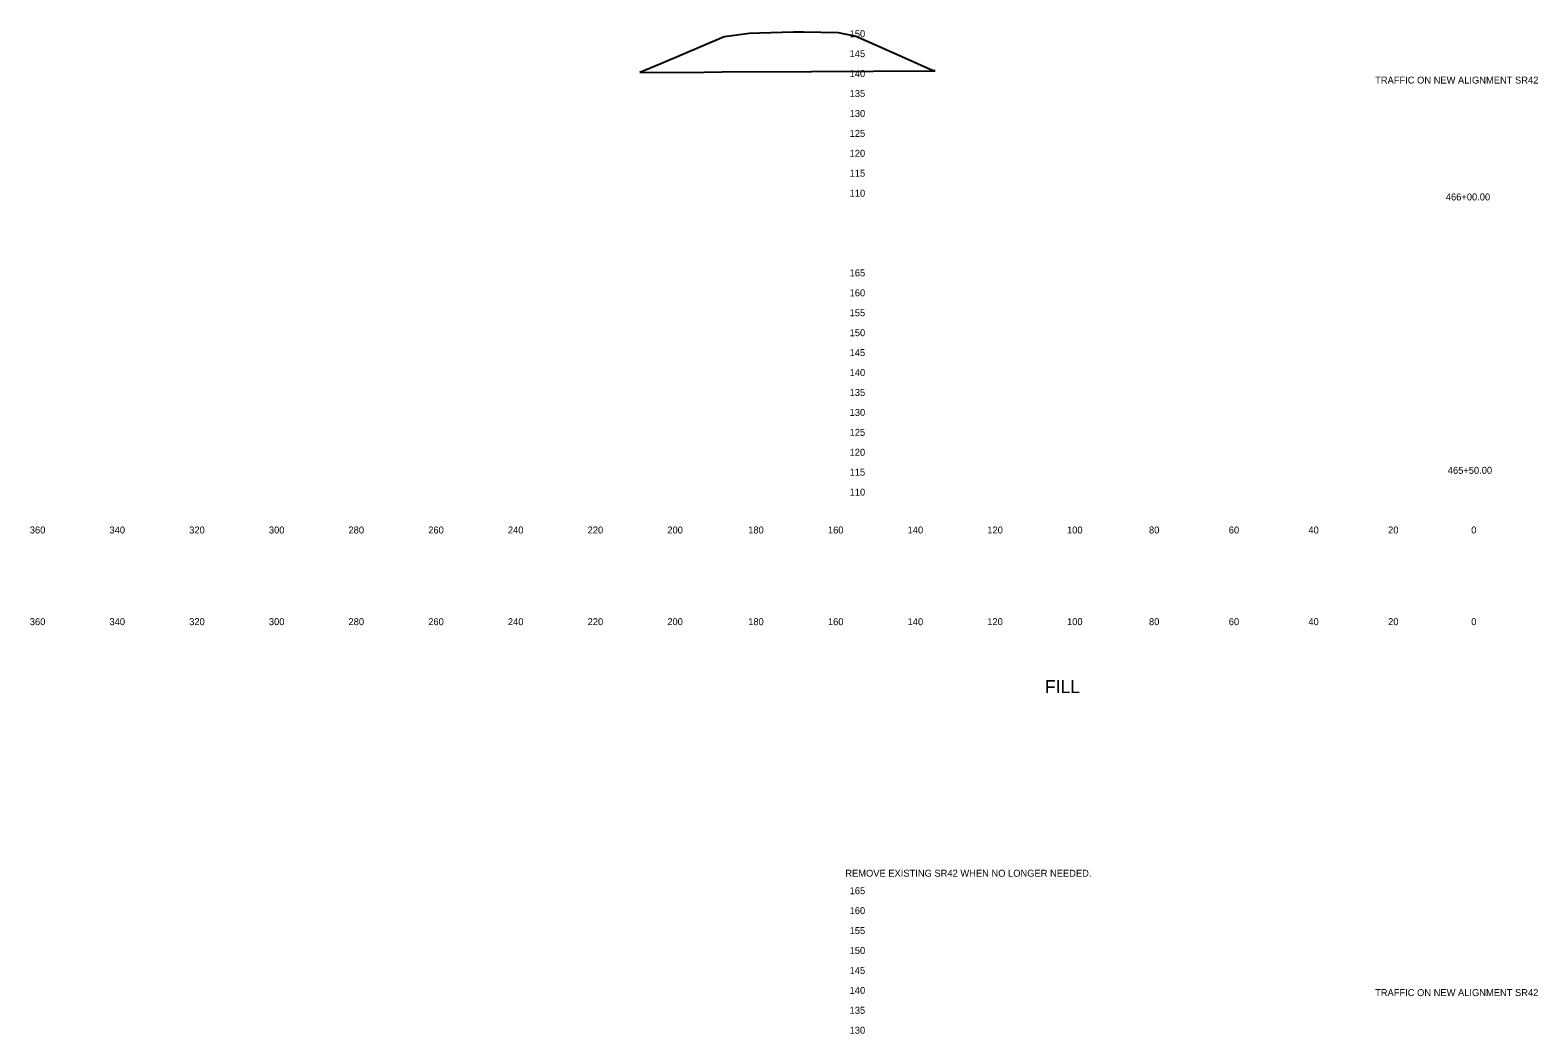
# Model space of a CAD drawing. Extents: x 21281 to 22024, y 6472 to 15208.
# Drawn here: x 21280.5 to 21658.8, y 8649.8 to 8901.6 of the extents above; entities that cross this region are included whole.
import ezdxf

# ---------------------------------------------------------------- set-up
doc = ezdxf.new("R2010")
doc.units = 0
for name, color, linetype in [('XS_SHEET_LABELS_ELEVATION', 7, 'Continuous'), ('XS_SHEET_LABELS_OFFSET', 7, 'Continuous'), ('XS_SHEET_LABELS_STATION', 7, 'Continuous'), ('XS_X_EXCESS', 7, 'Continuous')]:
    doc.layers.add(name, color=color, linetype=linetype)

msp = doc.modelspace()

# ---------------------------------------------------------------- linework, layer by layer
at = {"layer": 'XS_X_EXCESS'}
msp.add_line((21507.64, 8891.41), (21507.07, 8891.44), dxfattribs=at)
for points in [[(21507.07, 8891.44), (21495.34, 8896.65), (21487.51, 8900.14), (21484.92, 8900.63), (21483.38, 8900.95), (21474.61, 8901.09), (21472.04, 8901.15), (21463.53, 8900.89), (21460.9, 8900.81), (21455.98, 8900.1), (21454.68, 8899.97), (21438.79, 8893.18), (21433.47, 8891.02)], [(21433.47, 8891.02), (21449.64, 8891.11), (21454.14, 8891.14), (21476.57, 8891.26), (21507.64, 8891.41)]]:
    msp.add_lwpolyline(points, dxfattribs=at)

# ---------------------------------------------------------------- texts
at = {"layer": 'XS_SHEET_LABELS_ELEVATION'}
for s, p in [('  150  ', (21484.84, 8899.84)), ('  145  ', (21484.84, 8894.84)), ('  140  ', (21484.84, 8889.84)), ('  135  ', (21484.84, 8884.84)), ('  130  ', (21484.84, 8879.84)), ('  125  ', (21484.84, 8874.84)), ('  120  ', (21484.84, 8869.84)), ('  115  ', (21484.84, 8864.84)), ('  110  ', (21484.84, 8859.84)), ('  165  ', (21484.84, 8839.84)), ('  160  ', (21484.84, 8834.84)), ('  155  ', (21484.84, 8829.84)), ('  150  ', (21484.84, 8824.84)), ('  145  ', (21484.84, 8819.84)), ('  140  ', (21484.84, 8814.84)), ('  135  ', (21484.84, 8809.84)), ('  130  ', (21484.84, 8804.84)), ('  125  ', (21484.84, 8799.84)), ('  120  ', (21484.84, 8794.84)), ('  115  ', (21484.84, 8789.84)), ('  110  ', (21484.84, 8784.84)), ('  165  ', (21484.84, 8684.84)), ('  160  ', (21484.84, 8679.84)), ('  155  ', (21484.84, 8674.84)), ('  150  ', (21484.84, 8669.84)), ('  145  ', (21484.84, 8664.84)), ('  140  ', (21484.84, 8659.84)), ('  135  ', (21484.84, 8654.84)), ('  130  ', (21484.84, 8649.84))]:
    msp.add_text(s, height=1.75, dxfattribs=at).set_placement(p)
at = {"layer": 'XS_SHEET_LABELS_OFFSET'}
for s, height, p in [('  360  ', 1.75, (21279.14, 8775.34)), ('  340  ', 1.75, (21299.13, 8775.34)), ('  320  ', 1.75, (21319.13, 8775.34)), ('  300  ', 1.75, (21339.13, 8775.34)), ('  280  ', 1.75, (21359.1, 8775.34)), ('  260  ', 1.75, (21379.11, 8775.34)), ('  240  ', 1.75, (21399.1, 8775.34)), ('  220  ', 1.75, (21419.1, 8775.34)), ('  200  ', 1.75, (21439.1, 8775.34)), ('  180  ', 1.75, (21459.39, 8775.34)), ('  160  ', 1.75, (21479.4, 8775.34)), ('  140  ', 1.75, (21499.39, 8775.34)), ('  120  ', 1.75, (21519.39, 8775.34)), ('  100  ', 1.75, (21539.39, 8775.34)), ('  80  ', 1.75, (21559.95, 8775.34)), ('  60  ', 1.75, (21579.97, 8775.34)), ('  40  ', 1.75, (21599.95, 8775.34)), ('  20  ', 1.75, (21619.95, 8775.34)), ('  0  ', 1.75, (21640.81, 8775.34)), ('  0  ', 1.75, (21640.81, 8775.34)), ('  360  ', 1.75, (21279.14, 8752.34)), ('  340  ', 1.75, (21299.13, 8752.34)), ('  320  ', 1.75, (21319.13, 8752.34)), ('  300  ', 1.75, (21339.13, 8752.34)), ('  280  ', 1.75, (21359.1, 8752.34)), ('  260  ', 1.75, (21379.11, 8752.34)), ('  240  ', 1.75, (21399.1, 8752.34)), ('  220  ', 1.75, (21419.1, 8752.34)), ('  200  ', 1.75, (21439.1, 8752.34)), ('  180  ', 1.75, (21459.39, 8752.34)), ('  160  ', 1.75, (21479.4, 8752.34)), ('  140  ', 1.75, (21499.39, 8752.34)), ('  120  ', 1.75, (21519.39, 8752.34)), ('  100  ', 1.75, (21539.39, 8752.34)), ('  80  ', 1.75, (21559.95, 8752.34)), ('  60  ', 1.75, (21579.97, 8752.34)), ('  40  ', 1.75, (21599.95, 8752.34)), ('  20  ', 1.75, (21619.95, 8752.34)), ('  0  ', 1.75, (21640.81, 8752.34)), ('  0  ', 1.75, (21640.81, 8752.34)), ('FILL', 3.273, (21535.18, 8735.29))]:
    msp.add_text(s, height=height, dxfattribs=at).set_placement(p)
at = {"layer": 'XS_SHEET_LABELS_STATION'}
for s, p in [('TRAFFIC ON NEW ALIGNMENT SR42', (21617.99, 8888.21)), ('  466+00.00  ', (21634.43, 8858.89)), ('  465+50.00  ', (21634.92, 8790.31)), ('REMOVE EXISTING SR42 WHEN NO LONGER NEEDED.', (21485.06, 8689.23)), ('TRAFFIC ON NEW ALIGNMENT SR42', (21617.99, 8659.28))]:
    msp.add_text(s, height=1.75, dxfattribs=at).set_placement(p)

doc.saveas('drawing.dxf')
